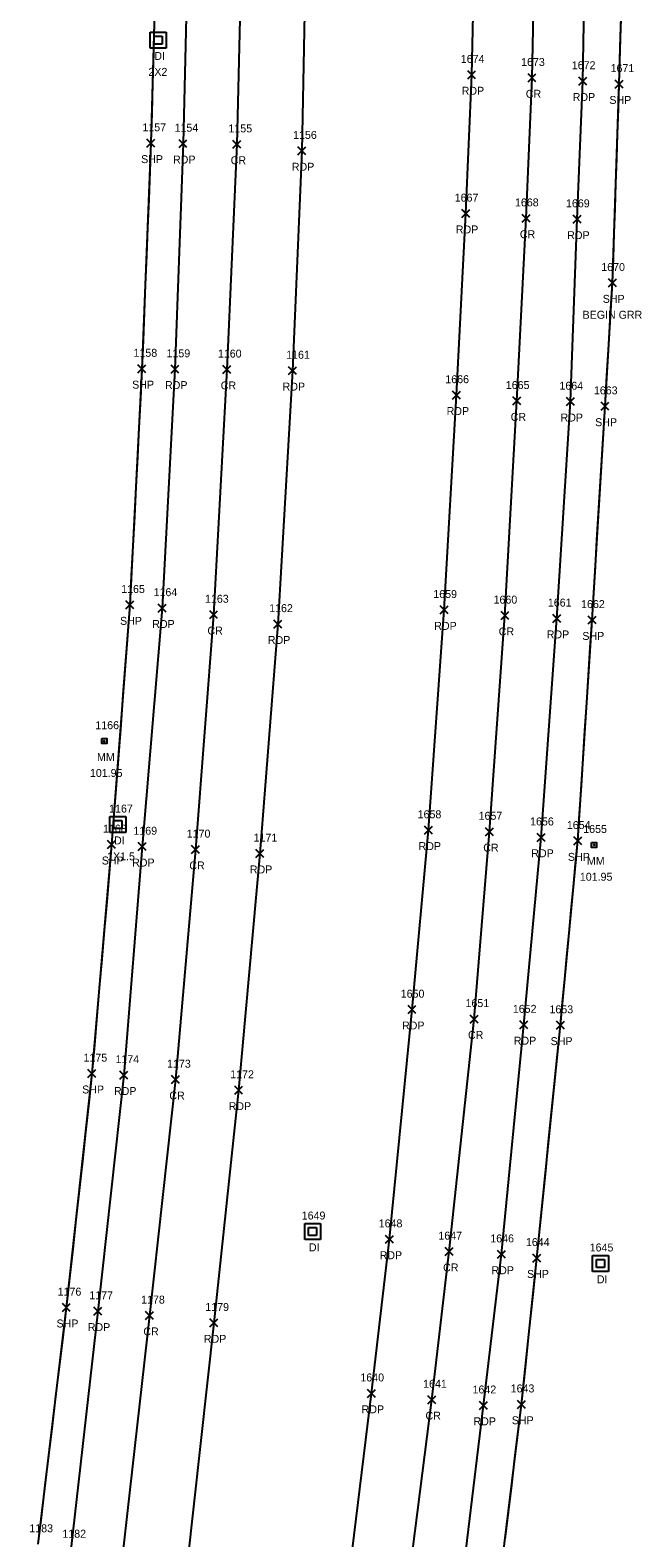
# Model space of a CAD drawing. Extents: x 1472022 to 1479249, y 777216 to 786527.
# Drawn here: x 1473880.6 to 1474034.3, y 781174.4 to 781553.3 of the extents above; entities that cross this region are included whole.
import ezdxf

# ---------------------------------------------------------------- set-up
doc = ezdxf.new("R2010")
doc.units = 0
for name, color, linetype in [('D_A', 7, 'Continuous'), ('D_C', 7, 'Continuous'), ('D_I', 7, 'Continuous'), ('DS', 7, 'Continuous'), ('LSOGP', 7, 'Continuous'), ('P_A', 7, 'Continuous'), ('P_C', 7, 'Continuous'), ('P_I', 7, 'Continuous'), ('P_TIC', 7, 'Continuous'), ('PET', 7, 'Continuous'), ('PRC', 7, 'Continuous'), ('PSP', 7, 'Continuous'), ('S_A', 7, 'Continuous'), ('S_C', 7, 'Continuous'), ('S_I', 7, 'Continuous'), ('SRM', 7, 'Continuous')]:
    doc.layers.add(name, color=color, linetype=linetype)

msp = doc.modelspace()

# ---------------------------------------------------------------- linework, layer by layer
at = {"layer": 'DS'}
for p, q in [((1473910.73, 781552.84), (1473914.73, 781552.84)), ((1473910.73, 781548.84), (1473910.73, 781552.84)), ((1473914.73, 781552.84), (1473914.73, 781548.84)), ((1473914.73, 781548.84), (1473910.73, 781548.84)), ((1473911.73, 781549.84), (1473911.73, 781551.84)), ((1473911.73, 781551.84), (1473913.73, 781551.84)), ((1473913.73, 781549.84), (1473911.73, 781549.84)), ((1473912.73, 781550.84), (1473912.73, 781550.84)), ((1473912.73, 781550.84), (1473912.73, 781550.84)), ((1473913.73, 781551.84), (1473913.73, 781549.84)), ((1473900.61, 781355.67), (1473904.61, 781355.67)), ((1473900.61, 781351.67), (1473900.61, 781355.67)), ((1473904.61, 781355.67), (1473904.61, 781351.67)), ((1473904.61, 781351.67), (1473900.61, 781351.67)), ((1473901.61, 781352.67), (1473901.61, 781354.67)), ((1473901.61, 781354.67), (1473903.61, 781354.67)), ((1473903.61, 781352.67), (1473901.61, 781352.67)), ((1473902.62, 781353.67), (1473902.62, 781353.67)), ((1473902.62, 781353.67), (1473902.62, 781353.67)), ((1473903.61, 781354.67), (1473903.61, 781352.67)), ((1473949.57, 781253.38), (1473953.57, 781253.38)), ((1473949.57, 781249.38), (1473949.57, 781253.38)), ((1473953.57, 781253.38), (1473953.57, 781249.38)), ((1473953.57, 781249.38), (1473949.57, 781249.38)), ((1473950.57, 781250.38), (1473950.57, 781252.38)), ((1473950.57, 781252.38), (1473952.57, 781252.38)), ((1473952.57, 781250.38), (1473950.57, 781250.38)), ((1473951.58, 781251.39), (1473951.58, 781251.39)), ((1473951.58, 781251.39), (1473951.58, 781251.39)), ((1473952.57, 781252.38), (1473952.57, 781250.38)), ((1474021.9, 781245.36), (1474025.9, 781245.36)), ((1474021.9, 781241.36), (1474021.9, 781245.36)), ((1474022.9, 781242.36), (1474022.9, 781244.36)), ((1474022.9, 781244.36), (1474024.9, 781244.36)), ((1474024.9, 781242.36), (1474022.9, 781242.36)), ((1474023.91, 781243.36), (1474023.91, 781243.36)), ((1474023.91, 781243.36), (1474023.91, 781243.36)), ((1474024.9, 781244.36), (1474024.9, 781242.36)), ((1474025.9, 781245.36), (1474025.9, 781241.36)), ((1474025.9, 781241.36), (1474021.9, 781241.36))]:
    msp.add_line(p, q, dxfattribs=at)
at = {"layer": 'LSOGP'}
for points in [[(1473999.91, 781174.08), (1474000.74, 781180.85), (1474001.57, 781187.62), (1474002.4, 781194.39), (1474003.23, 781201.16), (1474004.06, 781207.93), (1474005.02, 781217.12), (1474005.98, 781226.32), (1474006.94, 781235.51), (1474007.89, 781244.71), (1474008.63, 781252.02), (1474009.37, 781259.34), (1474010.11, 781266.65), (1474010.85, 781273.97), (1474011.59, 781281.28), (1474012.33, 781288.59), (1474013.07, 781295.91), (1474013.81, 781303.22), (1474014.36, 781309.01), (1474014.9, 781314.8), (1474015.44, 781320.59), (1474015.99, 781326.38), (1474016.53, 781332.17), (1474017.08, 781337.96), (1474017.62, 781343.75), (1474018.17, 781349.54), (1474018.62, 781356.48), (1474019.07, 781363.42), (1474019.52, 781370.36), (1474019.97, 781377.3), (1474020.43, 781384.25), (1474020.88, 781391.19), (1474021.33, 781398.13), (1474021.78, 781405.07), (1474022.19, 781411.79), (1474022.59, 781418.5), (1474023, 781425.22), (1474023.4, 781431.93), (1474023.81, 781438.65), (1474024.21, 781445.36), (1474024.61, 781452.08), (1474025.02, 781458.79), (1474025.49, 781466.54), (1474025.96, 781474.29), (1474026.43, 781482.04), (1474026.9, 781489.79), (1474027.11, 781496.04), (1474027.32, 781502.29), (1474027.54, 781508.54), (1474027.75, 781514.78), (1474027.96, 781521.03), (1474028.17, 781527.28), (1474028.38, 781533.53), (1474028.59, 781539.78), (1474028.77, 781545.84), (1474028.95, 781551.9), (1474029.13, 781557.95)], [(1473911.79, 781555.16), (1473911.57, 781547.6), (1473911.36, 781540.04), (1473911.15, 781532.48), (1473910.66, 781517.83), (1473910.38, 781510.74), (1473910.1, 781503.65), (1473909.82, 781496.57), (1473909.53, 781489.48), (1473909.25, 781482.4), (1473908.97, 781475.31), (1473908.31, 781460.81), (1473907.93, 781453.39), (1473907.55, 781445.96), (1473907.17, 781438.54), (1473906.79, 781431.12), (1473906.4, 781423.7), (1473906.02, 781416.28), (1473905.64, 781408.86), (1473905.07, 781401.33), (1473904.5, 781393.8), (1473903.92, 781386.27), (1473903.35, 781378.74), (1473902.78, 781371.21), (1473902.21, 781363.68), (1473901.63, 781356.15), (1473901.06, 781348.62), (1473900.44, 781341.43), (1473899.83, 781334.23), (1473899.21, 781327.04), (1473898.6, 781319.85), (1473897.98, 781312.65), (1473897.36, 781305.46), (1473896.75, 781298.27), (1473896.13, 781291.07), (1473895.33, 781283.72), (1473894.52, 781276.37), (1473893.72, 781269.02), (1473892.91, 781261.67), (1473892.11, 781254.31), (1473891.3, 781246.96), (1473890.5, 781239.61), (1473888.8, 781224.82), (1473887.9, 781217.39), (1473887.01, 781209.95), (1473886.11, 781202.52), (1473885.21, 781195.08), (1473884.32, 781187.65), (1473883.42, 781180.21), (1473882.53, 781172.78)]]:
    msp.add_lwpolyline(points, dxfattribs=at)
at = {"layer": 'P_TIC'}
for points in [[(1473990.52, 781541.09), (1473992.52, 781543.09)], [(1473992.52, 781541.09), (1473990.52, 781543.09)], [(1474005.68, 781540.33), (1474007.68, 781542.33)], [(1474007.68, 781540.33), (1474005.68, 781542.33)], [(1474018.41, 781539.51), (1474020.41, 781541.51)], [(1474020.41, 781539.51), (1474018.41, 781541.51)], [(1474027.59, 781538.78), (1474029.59, 781540.78)], [(1474029.59, 781538.78), (1474027.59, 781540.78)], [(1473909.94, 781523.91), (1473911.94, 781525.91)], [(1473911.94, 781523.91), (1473909.94, 781525.91)], [(1473918, 781523.8), (1473920, 781525.8)], [(1473920, 781523.8), (1473918, 781525.8)], [(1473931.54, 781523.63), (1473933.54, 781525.63)], [(1473933.54, 781523.63), (1473931.54, 781525.63)], [(1473947.84, 781521.99), (1473949.84, 781523.99)], [(1473949.84, 781521.99), (1473947.84, 781523.99)], [(1473989.05, 781506.23), (1473991.05, 781508.23)], [(1473991.05, 781506.23), (1473989.05, 781508.23)], [(1474004.19, 781505.03), (1474006.19, 781507.03)], [(1474006.19, 781505.03), (1474004.19, 781507.03)], [(1474017.02, 781504.8), (1474019.02, 781506.8)], [(1474019.02, 781504.8), (1474017.02, 781506.8)], [(1474025.9, 781488.79), (1474027.9, 781490.79)], [(1474027.9, 781488.79), (1474025.9, 781490.79)], [(1473907.69, 781467.23), (1473909.69, 781469.23)], [(1473909.69, 781467.23), (1473907.69, 781469.23)], [(1473915.99, 781467.11), (1473917.99, 781469.11)], [(1473917.99, 781467.11), (1473915.99, 781469.11)], [(1473929.03, 781467.03), (1473931.03, 781469.03)], [(1473931.03, 781467.03), (1473929.03, 781469.03)], [(1473945.53, 781466.74), (1473947.53, 781468.74)], [(1473947.53, 781466.74), (1473945.53, 781468.74)], [(1473986.74, 781460.59), (1473988.74, 781462.59)], [(1473988.74, 781460.59), (1473986.74, 781462.59)], [(1474001.87, 781459.13), (1474003.87, 781461.13)], [(1474003.87, 781459.13), (1474001.87, 781461.13)], [(1474015.36, 781458.96), (1474017.36, 781460.96)], [(1474017.36, 781458.96), (1474015.36, 781460.96)], [(1474024.02, 781457.79), (1474026.02, 781459.79)], [(1474026.02, 781457.79), (1474024.02, 781459.79)], [(1473904.64, 781407.86), (1473906.64, 781409.86)], [(1473906.64, 781407.86), (1473904.64, 781409.86)], [(1473912.78, 781407.07), (1473914.78, 781409.07)], [(1473914.78, 781407.07), (1473912.78, 781409.07)], [(1473983.63, 781406.6), (1473985.63, 781408.6)], [(1473985.63, 781406.6), (1473983.63, 781408.6)], [(1473925.7, 781405.41), (1473927.7, 781407.41)], [(1473927.7, 781405.41), (1473925.7, 781407.41)], [(1473941.83, 781403.05), (1473943.83, 781405.05)], [(1473943.83, 781403.05), (1473941.83, 781405.05)], [(1473998.89, 781405.19), (1474000.89, 781407.19)], [(1474000.89, 781405.19), (1473998.89, 781407.19)], [(1474011.88, 781404.45), (1474013.88, 781406.45)], [(1474013.88, 781404.45), (1474011.88, 781406.45)], [(1474020.78, 781404.07), (1474022.78, 781406.07)], [(1474022.78, 781404.07), (1474020.78, 781406.07)], [(1473979.69, 781351.24), (1473981.69, 781353.24)], [(1473981.69, 781351.24), (1473979.69, 781353.24)], [(1473995, 781350.86), (1473997, 781352.86)], [(1473997, 781350.86), (1473995, 781352.86)], [(1473900.06, 781347.62), (1473902.06, 781349.62)], [(1473902.06, 781347.62), (1473900.06, 781349.62)], [(1473907.72, 781347.11), (1473909.72, 781349.11)], [(1473909.72, 781347.11), (1473907.72, 781349.11)], [(1473921.16, 781346.38), (1473923.16, 781348.38)], [(1473923.16, 781346.38), (1473921.16, 781348.38)], [(1474008, 781349.44), (1474010, 781351.44)], [(1474010, 781349.44), (1474008, 781351.44)], [(1474017.17, 781348.54), (1474019.17, 781350.54)], [(1474019.17, 781348.54), (1474017.17, 781350.54)], [(1473937.3, 781345.37), (1473939.3, 781347.37)], [(1473939.3, 781345.37), (1473937.3, 781347.37)], [(1473975.53, 781306.15), (1473977.53, 781308.15)], [(1473977.53, 781306.15), (1473975.53, 781308.15)], [(1473991.15, 781303.78), (1473993.15, 781305.78)], [(1473993.15, 781303.78), (1473991.15, 781305.78)], [(1474003.6, 781302.34), (1474005.6, 781304.34)], [(1474005.6, 781302.34), (1474003.6, 781304.34)], [(1474012.81, 781302.22), (1474014.81, 781304.22)], [(1474014.81, 781302.22), (1474012.81, 781304.22)], [(1473895.13, 781290.07), (1473897.13, 781292.07)], [(1473897.13, 781290.07), (1473895.13, 781292.07)], [(1473903.17, 781289.69), (1473905.17, 781291.69)], [(1473905.17, 781289.69), (1473903.17, 781291.69)], [(1473916.13, 781288.55), (1473918.13, 781290.55)], [(1473918.13, 781288.55), (1473916.13, 781290.55)], [(1473931.98, 781285.88), (1473933.98, 781287.88)], [(1473933.98, 781285.88), (1473931.98, 781287.88)], [(1473969.91, 781248.41), (1473971.91, 781250.41)], [(1473971.91, 781248.41), (1473969.91, 781250.41)], [(1473984.9, 781245.34), (1473986.9, 781247.34)], [(1473986.9, 781245.34), (1473984.9, 781247.34)], [(1473998, 781244.64), (1474000, 781246.64)], [(1474000, 781244.64), (1473998, 781246.64)], [(1474006.89, 781243.71), (1474008.89, 781245.71)], [(1474008.89, 781243.71), (1474006.89, 781245.71)], [(1473888.69, 781231.26), (1473890.69, 781233.26)], [(1473890.69, 781231.26), (1473888.69, 781233.26)], [(1473896.58, 781230.34), (1473898.58, 781232.34)], [(1473898.58, 781230.34), (1473896.58, 781232.34)], [(1473909.61, 781229.26), (1473911.61, 781231.26)], [(1473911.61, 781229.26), (1473909.61, 781231.26)], [(1473925.74, 781227.4), (1473927.74, 781229.4)], [(1473927.74, 781227.4), (1473925.74, 781229.4)], [(1473965.39, 781209.69), (1473967.39, 781211.69)], [(1473967.39, 781209.69), (1473965.39, 781211.69)], [(1473980.49, 781208.1), (1473982.49, 781210.1)], [(1473982.49, 781208.1), (1473980.49, 781210.1)], [(1473993.49, 781206.67), (1473995.49, 781208.67)], [(1473995.49, 781206.67), (1473993.49, 781208.67)], [(1474003.06, 781206.93), (1474005.06, 781208.93)], [(1474005.06, 781206.93), (1474003.06, 781208.93)]]:
    msp.add_lwpolyline(points, dxfattribs=at)
at = {"layer": 'PET'}
for points in [[(1473936.65, 781984.46), (1473941.26, 781927.31), (1473945.01, 781870.98), (1473948.1, 781815.16), (1473949.78, 781761), (1473950.76, 781706.86), (1473950.83, 781644.05), (1473950.06, 781583.41), (1473948.84, 781522.99), (1473946.53, 781467.74), (1473942.83, 781404.05), (1473938.3, 781346.37), (1473932.98, 781286.88), (1473926.74, 781228.4), (1473920.04, 781167.79)], [(1473906.73, 781982.64), (1473911.24, 781925.62), (1473915.01, 781868.86), (1473918.09, 781814.94), (1473919.79, 781760.09), (1473921.16, 781706.54), (1473921.22, 781646.65), (1473920.46, 781584.88), (1473919, 781524.8), (1473916.99, 781468.11), (1473913.78, 781408.07), (1473908.72, 781348.11), (1473904.17, 781290.69), (1473897.58, 781231.34), (1473890.82, 781171.41)], [(1473988.2, 781155.74), (1473994.49, 781207.67), (1473999, 781245.64), (1474004.6, 781303.34), (1474009, 781350.44), (1474012.88, 781405.45), (1474016.36, 781459.96), (1474018.02, 781505.8), (1474019.41, 781540.51), (1474020.28, 781588.67), (1474020.92, 781637.94), (1474020.52, 781688.39), (1474019.85, 781737.76), (1474018.14, 781790.49), (1474015.87, 781842.28), (1474013.69, 781892.18), (1474009.96, 781943.03)], [(1473960.11, 781159.28), (1473966.39, 781210.69), (1473970.91, 781249.41), (1473976.53, 781307.15), (1473980.69, 781352.24), (1473984.63, 781407.6), (1473987.74, 781461.59), (1473990.05, 781507.23), (1473991.52, 781542.09), (1473992.62, 781591.22), (1473992.7, 781637.96), (1473992.74, 781689.53), (1473991.78, 781738.04), (1473989.99, 781788.4), (1473987.73, 781842.4), (1473985.44, 781889.72), (1473981.98, 781941.8)]]:
    msp.add_lwpolyline(points, dxfattribs=at)
at = {"layer": 'PRC'}
for points in [[(1473920.36, 781983.62), (1473924.52, 781926.3), (1473927.05, 781865.83), (1473931.41, 781814.87), (1473933.18, 781760.96), (1473934.49, 781707.12), (1473934.8, 781646.17), (1473933.94, 781584.19), (1473932.54, 781524.63), (1473930.03, 781468.03), (1473926.7, 781406.41), (1473922.16, 781347.38), (1473917.13, 781289.55), (1473910.61, 781230.26), (1473903.7, 781169.35)], [(1473975.01, 781157.69), (1473981.49, 781209.1), (1473985.9, 781246.34), (1473992.15, 781304.78), (1473996, 781351.86), (1473999.89, 781406.19), (1474002.87, 781460.13), (1474005.19, 781506.03), (1474006.68, 781541.33), (1474007.72, 781590.12), (1474008.1, 781637.49), (1474007.9, 781688.82), (1474007.05, 781737.83), (1474005.11, 781789.12), (1474002.79, 781842.22), (1474000.48, 781890.51), (1473996.64, 781942.33)]]:
    msp.add_lwpolyline(points, dxfattribs=at)
at = {"layer": 'PSP'}
for points in [[(1473899.44, 781982.31), (1473904.16, 781925.33), (1473907.68, 781869.38), (1473909.81, 781815.4), (1473911.78, 781760.13), (1473912.79, 781706.67), (1473913.35, 781646.55), (1473912.63, 781585.42), (1473910.94, 781524.91), (1473908.69, 781468.23), (1473905.64, 781408.86), (1473901.06, 781348.62), (1473896.13, 781291.07), (1473889.69, 781232.26), (1473882.53, 781172.78)], [(1473997.41, 781153.76), (1474004.06, 781207.93), (1474007.89, 781244.71), (1474013.81, 781303.22), (1474018.17, 781349.54), (1474021.78, 781405.07), (1474025.02, 781458.79), (1474026.9, 781489.79), (1474028.59, 781539.78), (1474030.02, 781588.25), (1474030.24, 781637.7), (1474030.49, 781688.1), (1474029.89, 781738.22), (1474028.18, 781791.43), (1474026.06, 781843.25), (1474023.21, 781893.51), (1474019.96, 781943.82)]]:
    msp.add_lwpolyline(points, dxfattribs=at)
at = {"layer": 'SRM'}
for points in [[(1473898.58, 781375.26), (1473899.83, 781375.26), (1473899.83, 781374.01), (1473898.58, 781374.01)], [(1474021.66, 781349.17), (1474022.91, 781349.17), (1474022.91, 781347.92), (1474021.66, 781347.92)]]:
    msp.add_lwpolyline(points, close=True, dxfattribs=at)
for centre in [(1473899.21, 781374.63), (1474022.29, 781348.54)]:
    msp.add_circle(centre, 0.0833, dxfattribs=at)

# ---------------------------------------------------------------- texts
at = {"layer": 'D_A'}
for p in [(1473911.79, 781545.84), (1473901.67, 781348.67), (1473950.63, 781246.39), (1474022.96, 781238.36)]:
    msp.add_text('DI', height=2, dxfattribs=at).set_placement(p)
at = {"layer": 'D_C'}
for s, p in [('2X2', (1473910.31, 781541.84)), ('1X1.5', (1473899.94, 781344.67))]:
    msp.add_text(s, height=2, dxfattribs=at).set_placement(p)
at = {"layer": 'D_I'}
for s, p in [('1167', (1473900.44, 781356.67)), ('1649', (1473948.83, 781254.39)), ('1645', (1474021.17, 781246.36))]:
    msp.add_text(s, height=2, dxfattribs=at).set_placement(p)
at = {"layer": 'P_A'}
for s, p in [('RDP', (1473989.01, 781537.09)), ('CR', (1474005.12, 781536.33)), ('RDP', (1474016.9, 781535.51)), ('SHP', (1474026.12, 781534.78)), ('SHP', (1473908.48, 781519.91)), ('RDP', (1473916.49, 781519.8)), ('CR', (1473930.98, 781519.63)), ('RDP', (1473946.33, 781517.99)), ('RDP', (1473987.54, 781502.23)), ('CR', (1474003.62, 781501.03)), ('RDP', (1474015.51, 781500.8)), ('SHP', (1474024.44, 781484.79)), ('SHP', (1473906.23, 781463.23)), ('RDP', (1473914.48, 781463.11)), ('CR', (1473928.47, 781463.03)), ('RDP', (1473944.02, 781462.74)), ('RDP', (1473985.23, 781456.59)), ('CR', (1474001.31, 781455.13)), ('RDP', (1474013.84, 781454.96)), ('SHP', (1474022.55, 781453.79)), ('SHP', (1473903.18, 781403.86)), ('RDP', (1473911.27, 781403.07)), ('CR', (1473925.14, 781401.41)), ('RDP', (1473940.31, 781399.05)), ('RDP', (1473982.12, 781402.6)), ('CR', (1473998.32, 781401.19)), ('RDP', (1474010.37, 781400.45)), ('SHP', (1474019.32, 781400.07)), ('RDP', (1473978.18, 781347.24)), ('CR', (1473994.43, 781346.86)), ('SHP', (1473898.59, 781343.62)), ('RDP', (1473906.21, 781343.11)), ('CR', (1473920.59, 781342.38)), ('RDP', (1474006.49, 781345.44)), ('SHP', (1474015.7, 781344.54)), ('RDP', (1473935.79, 781341.37)), ('RDP', (1473974.02, 781302.15)), ('CR', (1473990.59, 781299.78)), ('RDP', (1474002.09, 781298.34)), ('SHP', (1474011.35, 781298.22)), ('SHP', (1473893.67, 781286.07)), ('RDP', (1473901.66, 781285.69)), ('CR', (1473915.56, 781284.55)), ('RDP', (1473930.47, 781281.88)), ('RDP', (1473968.4, 781244.41)), ('CR', (1473984.34, 781241.34)), ('RDP', (1473996.49, 781240.64)), ('SHP', (1474005.43, 781239.71)), ('SHP', (1473887.23, 781227.26)), ('RDP', (1473895.07, 781226.34)), ('CR', (1473909.04, 781225.26)), ('RDP', (1473924.23, 781223.4)), ('RDP', (1473963.87, 781205.69)), ('CR', (1473979.92, 781204.1)), ('RDP', (1473991.97, 781202.67)), ('SHP', (1474001.6, 781202.93))]:
    msp.add_text(s, height=2, dxfattribs=at).set_placement(p)
at = {"layer": 'P_C'}
msp.add_text('BEGIN GRR', height=2, dxfattribs=at).set_placement((1474019.38, 781480.79))
at = {"layer": 'P_I'}
for s, p in [('1674', (1473988.78, 781545.09)), ('1673', (1474003.94, 781544.33)), ('1672', (1474016.67, 781543.51)), ('1671', (1474026.42, 781542.78)), ('1157', (1473908.81, 781527.91)), ('1154', (1473916.88, 781527.8)), ('1155', (1473930.42, 781527.63)), ('1156', (1473946.66, 781525.99)), ('1667', (1473987.26, 781510.23)), ('1668', (1474002.4, 781509.03)), ('1669', (1474015.22, 781508.8)), ('1670', (1474024.08, 781492.79)), ('1158', (1473906.57, 781471.23)), ('1159', (1473914.86, 781471.11)), ('1160', (1473927.77, 781471.03)), ('1161', (1473944.92, 781470.74)), ('1666', (1473984.9, 781464.59)), ('1665', (1474000.09, 781463.13)), ('1664', (1474013.57, 781462.96)), ('1663', (1474022.23, 781461.79)), ('1165', (1473903.47, 781411.86)), ('1164', (1473911.61, 781411.07)), ('1659', (1473981.88, 781410.6)), ('1163', (1473924.53, 781409.41)), ('1162', (1473940.65, 781407.05)), ('1660', (1473997.02, 781409.19)), ('1661', (1474010.66, 781408.45)), ('1662', (1474019, 781408.07)), ('1658', (1473977.95, 781355.24)), ('1657', (1473993.26, 781354.86)), ('1656', (1474006.2, 781353.44)), ('1168', (1473898.89, 781351.62)), ('1169', (1473906.54, 781351.11)), ('1170', (1473919.94, 781350.38)), ('1654', (1474015.43, 781352.54)), ('1171', (1473936.74, 781349.37)), ('1650', (1473973.7, 781310.15)), ('1651', (1473989.98, 781307.78)), ('1652', (1474001.86, 781306.34)), ('1653', (1474011.07, 781306.22)), ('1175', (1473894.01, 781294.07)), ('1174', (1473902.04, 781293.69)), ('1173', (1473915, 781292.55)), ('1172', (1473930.86, 781289.88)), ('1648', (1473968.17, 781252.41)), ('1647', (1473983.16, 781249.34)), ('1646', (1473996.2, 781248.64)), ('1644', (1474005.15, 781247.71)), ('1176', (1473887.51, 781235.26)), ('1177', (1473895.46, 781234.34)), ('1178', (1473908.48, 781233.26)), ('1179', (1473924.61, 781231.4)), ('1640', (1473963.56, 781213.69)), ('1641', (1473979.32, 781212.1)), ('1642', (1473991.74, 781210.67)), ('1643', (1474001.32, 781210.93)), ('1183', (1473880.4, 781175.78)), ('1182', (1473888.7, 781174.41))]:
    msp.add_text(s, height=2, dxfattribs=at).set_placement(p)
at = {"layer": 'S_A'}
for p in [(1473897.4, 781369.63), (1474020.48, 781343.54)]:
    msp.add_text('MM', height=2, dxfattribs=at).set_placement(p)
at = {"layer": 'S_C'}
for p in [(1473895.62, 781365.63), (1474018.7, 781339.54)]:
    msp.add_text('101.95', height=2, dxfattribs=at).set_placement(p)
at = {"layer": 'S_I'}
for s, p in [('1166', (1473896.98, 781377.63)), ('1655', (1474019.55, 781351.54))]:
    msp.add_text(s, height=2, dxfattribs=at).set_placement(p)

doc.saveas('drawing.dxf')
